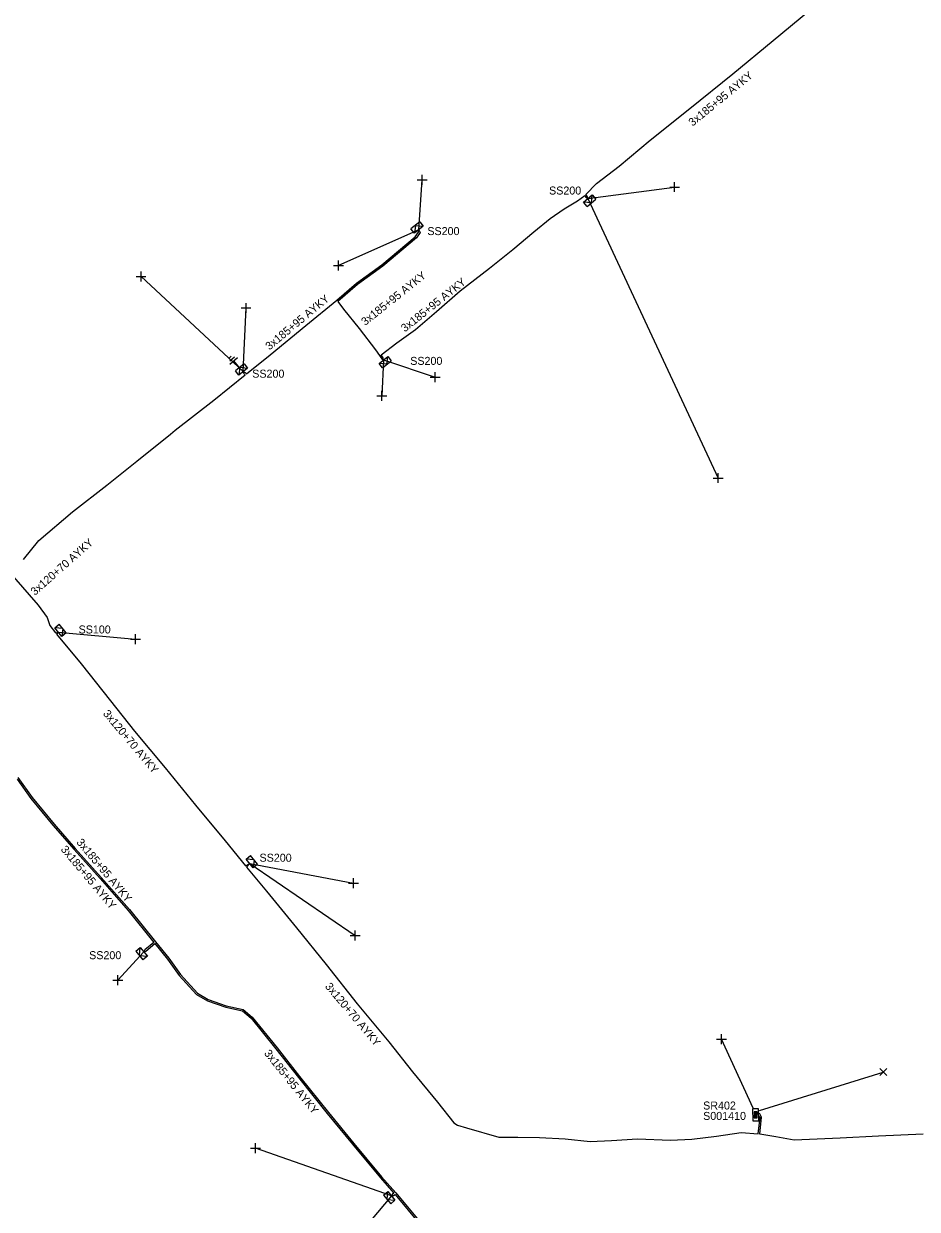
# Model space of a CAD drawing. Extents: x -763093 to -760976, y -1155572 to -1152009.
# Drawn here: x -762555.8 to -762444.1, y -1154837.4 to -1154689.2 of the extents above; entities that cross this region are included whole.
import ezdxf

# ---------------------------------------------------------------- set-up
doc = ezdxf.new("R2010")
doc.units = 0
for name, color, linetype in [('Vrstva 1', 7, 'Continuous'), ('Vrstva 14', 7, 'Continuous'), ('Vrstva 15', 7, 'Continuous'), ('Vrstva 28', 7, 'Continuous'), ('Vrstva 29', 7, 'Continuous'), ('Vrstva 30', 7, 'Continuous'), ('Vrstva 31', 7, 'Continuous'), ('Vrstva 33', 7, 'Continuous'), ('Vrstva 34', 7, 'Continuous'), ('Vrstva 5', 7, 'Continuous'), ('Vrstva 59', 7, 'Continuous'), ('Vrstva 6', 7, 'Continuous'), ('Vrstva 8', 7, 'Continuous'), ('Vrstva 9', 7, 'Continuous')]:
    doc.layers.add(name, color=color, linetype=linetype)

# ---------------------------------------------------------------- blocks, each defined once
blk = doc.blocks.new('NN800')
at = {"layer": 'Vrstva 1'}
for points in [[(-0.44, 0.44), (0.44, -0.44)], [(-0.44, -0.44), (0.44, 0.44)]]:
    blk.add_lwpolyline(points, dxfattribs=at)
blk = doc.blocks.new('NN620')
at = {"layer": 'Vrstva 8'}
for points in [[(0.75, 0), (-0.75, 0)], [(-0.75, 0), (-0.75, -0.75)], [(0.75, -0.75), (0.75, 0)], [(-0.75, -0.75), (0.75, -0.75)], [(0.37, -0.18), (-0.38, -0.18)], [(-0.38, -0.18), (-0.38, -0.56)], [(-0.38, -0.56), (0.37, -0.56)], [(0.32, -0.23), (-0.33, -0.23)], [(-0.33, -0.23), (-0.33, -0.51)], [(-0.33, -0.51), (0.32, -0.51)], [(0.27, -0.27), (-0.28, -0.27)], [(-0.28, -0.27), (-0.28, -0.46)], [(-0.28, -0.46), (0.27, -0.46)], [(0.23, -0.32), (-0.23, -0.32)], [(-0.23, -0.32), (-0.23, -0.42)], [(-0.23, -0.42), (0.23, -0.42)], [(-0.19, -0.37), (0.19, -0.37)], [(0.23, -0.42), (0.23, -0.32)], [(0.27, -0.46), (0.27, -0.27)], [(0.32, -0.51), (0.32, -0.23)], [(0.37, -0.56), (0.37, -0.18)]]:
    blk.add_lwpolyline(points, dxfattribs=at)
blk = doc.blocks.new('NN630')
at = {"layer": 'Vrstva 9'}
for points in [[(0, -0.7), (-0.7, 0)], [(-0.7, -0.7), (-0.7, 0), (0.7, 0), (0.7, -0.7)], [(-0.7, -0.7), (0.7, -0.7)], [(0, -0.7), (0.7, 0)]]:
    blk.add_lwpolyline(points, dxfattribs=at)
blk = doc.blocks.new('NN810')
at = {"layer": 'Vrstva 14'}
for points in [[(0, -0.64), (0, -1.89)], [(0.63, -1.89), (-0.62, -1.89)], [(0.39, -2.2), (-0.4, -2.2)], [(0, -2.52), (-0.12, -2.52)], [(0.14, -2.52), (0, -2.52)]]:
    blk.add_lwpolyline(points, dxfattribs=at)

msp = doc.modelspace()

# ---------------------------------------------------------------- linework, layer by layer
at = {"layer": 'Vrstva 5'}
for points in [[(-762555.82, -1154756.17), (-762553.9, -1154753.81), (-762549.69, -1154750.21), (-762545.37, -1154746.88), (-762541.63, -1154743.89), (-762537.45, -1154740.5), (-762536.84, -1154740.01), (-762532.01, -1154736.26), (-762528.1, -1154733.12), (-762528.26, -1154732.94), (-762528.34, -1154732.7), (-762528.1, -1154732.82), (-762527.94, -1154733), (-762525, -1154730.59), (-762520.54, -1154726.93), (-762516.67, -1154723.79), (-762514.18, -1154721.66), (-762511.02, -1154719.37), (-762506.85, -1154715.85), (-762506.45, -1154715.26), (-762506.4, -1154714.97), (-762506.23, -1154715.3), (-762506.7, -1154716), (-762510.9, -1154719.53), (-762514.06, -1154721.82), (-762516.54, -1154723.95), (-762515.83, -1154724.88), (-762513.87, -1154727.33), (-762511.82, -1154729.99), (-762511.03, -1154731.11), (-762510.83, -1154731.24), (-762510.87, -1154730.99), (-762511.13, -1154730.59), (-762509.15, -1154729.09), (-762506.83, -1154727.44), (-762504.21, -1154725.19), (-762501.23, -1154722.61), (-762497.56, -1154719.79), (-762494.66, -1154717.45), (-762492.02, -1154715.24), (-762490, -1154713.57), (-762488.24, -1154712.37), (-762486.6, -1154711.37), (-762485.68, -1154710.68), (-762485.52, -1154710.9), (-762485.27, -1154711.06), (-762485.36, -1154710.77), (-762485.53, -1154710.55), (-762484.2, -1154709.17), (-762481.38, -1154707.02), (-762477.48, -1154703.77), (-762472.55, -1154699.8), (-762467.19, -1154695.5), (-762462.15, -1154691.31), (-762457.55, -1154687.51)], [(-762557.04, -1154758.36), (-762553.99, -1154761.88), (-762552.85, -1154763.42), (-762552.5, -1154764.43), (-762551.82, -1154765.37), (-762551.45, -1154765.27), (-762551.69, -1154765.53), (-762548.58, -1154769.24), (-762544.94, -1154773.87), (-762541.93, -1154777.64), (-762538.12, -1154782.24), (-762534.33, -1154786.89), (-762530.61, -1154791.36), (-762528.06, -1154794.48), (-762527.53, -1154794.18), (-762527.94, -1154794.64), (-762525.42, -1154797.64), (-762521.69, -1154802.23), (-762517.99, -1154806.81), (-762514.11, -1154811.7), (-762510.16, -1154816.49), (-762507.18, -1154820.2), (-762504.09, -1154824.02), (-762502.05, -1154826.59), (-762501.58, -1154826.88), (-762500.45, -1154827.22), (-762496.4, -1154828.39), (-762494.04, -1154828.37), (-762491.34, -1154828.42), (-762488.11, -1154828.6), (-762484.99, -1154828.91), (-762482.35, -1154828.81), (-762479.07, -1154828.59), (-762474.95, -1154828.78), (-762472.31, -1154828.65), (-762469.2, -1154828.24), (-762466.13, -1154827.81), (-762464, -1154827.96), (-762463.77, -1154825.94), (-762463.84, -1154825.8)], [(-762556.61, -1154783.64), (-762554.89, -1154786.06), (-762552.15, -1154789.4), (-762549.47, -1154792.45), (-762546.23, -1154796.07), (-762542.72, -1154800.05), (-762539.51, -1154804.04), (-762540.63, -1154804.97), (-762540.77, -1154805.23), (-762540.51, -1154805.13), (-762539.38, -1154804.19), (-762537.8, -1154806.14), (-762536.36, -1154808.17), (-762534.18, -1154810.56), (-762532.82, -1154811.35), (-762530.53, -1154812.15), (-762528.45, -1154812.59), (-762527.35, -1154813.51), (-762524.28, -1154817.34), (-762521.46, -1154820.91), (-762517.85, -1154825.42), (-762514.7, -1154829.28), (-762511.21, -1154833.48), (-762509.51, -1154835.39), (-762509.7, -1154835.52), (-762509.83, -1154835.73), (-762509.58, -1154835.68), (-762509.38, -1154835.54), (-762506.33, -1154839.21)], [(-762556.53, -1154783.44), (-762554.73, -1154785.94), (-762551.99, -1154789.28), (-762549.33, -1154792.31), (-762546.09, -1154795.93), (-762542.56, -1154799.93), (-762539.29, -1154803.99), (-762537.64, -1154806.02), (-762536.2, -1154808.05), (-762534.06, -1154810.4), (-762532.74, -1154811.17), (-762530.47, -1154811.95), (-762528.35, -1154812.41), (-762527.21, -1154813.37), (-762524.12, -1154817.22), (-762521.3, -1154820.79), (-762517.69, -1154825.3), (-762514.54, -1154829.16), (-762511.06, -1154833.33), (-762509.29, -1154835.34), (-762506.17, -1154839.09)], [(-762443.38, -1154827.99), (-762448.95, -1154828.26), (-762453.76, -1154828.49), (-762459.5, -1154828.74), (-762461.78, -1154828.35), (-762463.8, -1154827.99), (-762463.57, -1154825.88), (-762463.86, -1154825.39)]]:
    msp.add_lwpolyline(points, dxfattribs=at)
at = {"layer": 'Vrstva 59'}
for points in [[(-762506.4, -1154714.97), (-762506, -1154708.75)], [(-762485.27, -1154711.06), (-762474.44, -1154709.63)], [(-762485.27, -1154711.06), (-762469, -1154746)], [(-762506.4, -1154714.97), (-762516.45, -1154719.43)], [(-762528.34, -1154732.7), (-762541.12, -1154720.83)], [(-762528.34, -1154732.7), (-762528, -1154724.75)], [(-762510.83, -1154731.24), (-762511.04, -1154735.72)], [(-762510.83, -1154731.24), (-762504.38, -1154733.38)], [(-762551.45, -1154765.27), (-762541.81, -1154766.13)], [(-762527.53, -1154794.18), (-762514.35, -1154803.17)], [(-762527.53, -1154794.18), (-762514.56, -1154796.63)], [(-762540.77, -1154805.23), (-762544, -1154808.75)], [(-762464.62, -1154824.76), (-762468.58, -1154816.15)], [(-762463.83, -1154825.05), (-762448.38, -1154820.25)], [(-762509.83, -1154835.73), (-762526.81, -1154829.75)], [(-762509.83, -1154835.73), (-762513.31, -1154839.9)]]:
    msp.add_lwpolyline(points, dxfattribs=at)

# ---------------------------------------------------------------- block references
at = {"layer": 'Vrstva 15', "rotation": -139.6349138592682}
msp.add_blockref('NN810', (-762528.31, -1154732.79), dxfattribs=at)
at = {"layer": 'Vrstva 28', "rotation": -89.596819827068}
msp.add_blockref('NN620', (-762463.94, -1154825.59), dxfattribs=at)
at = {"layer": 'Vrstva 31'}
for p, rotation in [((-762485.27, -1154711.06), 39.31787501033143), ((-762506.4, -1154714.97), -140.87020821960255), ((-762510.83, -1154731.24), 38.228436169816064), ((-762528.34, -1154732.7), -141.32934939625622), ((-762551.45, -1154765.27), 129.1657750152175), ((-762527.53, -1154794.18), 129.29501670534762), ((-762540.77, -1154805.23), -50.85348604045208), ((-762509.83, -1154835.73), -50.40057223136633)]:
    msp.add_blockref('NN630', p, dxfattribs=dict(at, rotation=rotation))
at = {"layer": 'Vrstva 34'}
for p, rotation in [((-762506, -1154708.75), 45), ((-762474.44, -1154709.63), 44.99999995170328), ((-762516.45, -1154719.43), 45), ((-762541.12, -1154720.83), 45), ((-762528, -1154724.75), 45), ((-762504.38, -1154733.38), 45), ((-762511.04, -1154735.72), 45), ((-762469, -1154746), 45), ((-762541.81, -1154766.13), 45), ((-762514.56, -1154796.63), 45), ((-762514.35, -1154803.17), 45), ((-762544, -1154808.75), 45), ((-762468.58, -1154816.15), 45), ((-762526.81, -1154829.75), 45)]:
    msp.add_blockref('NN800', p, dxfattribs=dict(at, rotation=rotation))
msp.add_blockref('NN800', (-762448.38, -1154820.25), dxfattribs=at)

# ---------------------------------------------------------------- texts
at = {"layer": 'Vrstva 29'}
msp.add_text('S001410', height=1, dxfattribs=at).set_placement((-762470.88, -1154826.23))
at = {"layer": 'Vrstva 30'}
msp.add_text('SR402', height=1, dxfattribs=at).set_placement((-762470.88, -1154824.93))
at = {"layer": 'Vrstva 33'}
for s, p in [('SS200', (-762490.13, -1154710.57)), ('SS200', (-762505.34, -1154715.64)), ('SS200', (-762507.48, -1154731.86)), ('SS200', (-762527.22, -1154733.46)), ('SS100', (-762548.92, -1154765.43)), ('SS200', (-762526.31, -1154793.96)), ('SS200', (-762547.6, -1154806.14))]:
    msp.add_text(s, height=1, dxfattribs=at).set_placement(p)
at = {"layer": 'Vrstva 6'}
for s, rotation, p in [('3x185+95 AYKY', 39.241, (-762472.2, -1154702.09)), ('3x185+95 AYKY', 38.491, (-762513.11, -1154727)), ('3x185+95 AYKY', 38.454, (-762508.15, -1154727.81)), ('3x185+95 AYKY', 39.804, (-762525.07, -1154730.07)), ('3x120+70 AYKY', 41.455, (-762554.38, -1154760.74)), ('3x120+70 AYKY', 310.021, (-762545.93, -1154775.49)), ('3x185+95 AYKY', 309.932, (-762549.25, -1154791.57)), ('3x185+95 AYKY', 309.927, (-762551.21, -1154792.45)), ('3x120+70 AYKY', 310.073, (-762518.19, -1154809.58)), ('3x185+95 AYKY', 308.838, (-762525.8, -1154817.93))]:
    msp.add_text(s, height=1, rotation=rotation, dxfattribs=at).set_placement(p)

doc.saveas('drawing.dxf')
